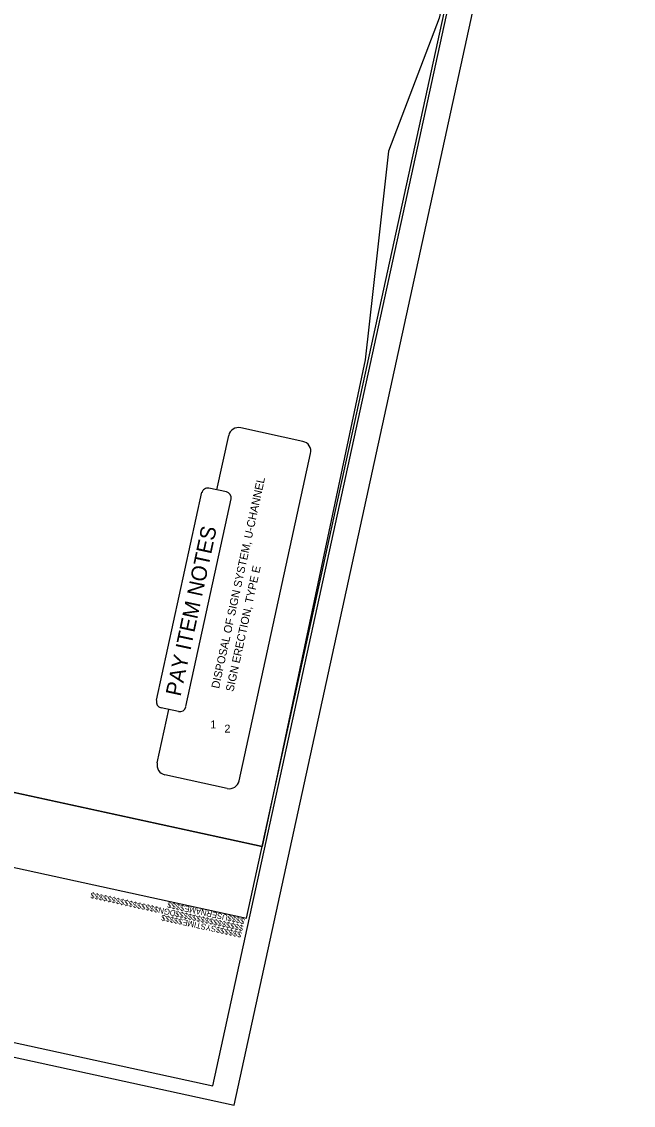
# Model space of a CAD drawing. Extents: x 1615829 to 1617263, y 900664 to 902544.
# Drawn here: x 1616713 to 1617263, y 900664 to 901639 of the extents above; entities that cross this region are included whole.
import ezdxf

# ---------------------------------------------------------------- set-up
doc = ezdxf.new("R2010")
doc.units = 0
for name, color, linetype in [('CTL Primary Horizontal and Vertical CELL', 7, 'Continuous'), ('CTL Primary Horizontal and Vertical Cogo Number', 7, 'Continuous'), ('CTL Secondary Horizontal and Vertical CELL', 7, 'Continuous'), ('Default', 7, 'Continuous'), ('Exist DTM Crownline Cogo Number', 7, 'Continuous'), ('Exist Roads Curbs Cogo Point CELL', 7, 'Continuous'), ('Exist Structure Minor Pipes RCP 18 Inch Cogo Point CELL', 7, 'Continuous')]:
    doc.layers.add(name, color=color, linetype=linetype)

msp = doc.modelspace()

# ---------------------------------------------------------------- linework, layer by layer
at = {"layer": 'CTL Primary Horizontal and Vertical CELL'}
msp.add_lwpolyline([(1616208.96, 902534.66), (1615853.55, 900906.5), (1616884.38, 900681.48), (1617239.79, 902309.64)], close=True, dxfattribs=at)
at = {"layer": 'CTL Primary Horizontal and Vertical Cogo Number'}
msp.add_lwpolyline([(1616187.99, 902543.84), (1615828.85, 900898.58), (1616903.54, 900663.99), (1617262.68, 902309.25)], close=True, dxfattribs=at)
at = {"layer": 'CTL Secondary Horizontal and Vertical CELL'}
msp.add_lwpolyline([(1616208.79, 902521.9), (1615888.89, 901056.41), (1616914.73, 900832.48), (1617234.63, 902297.97)], close=True, dxfattribs=at)
at = {"layer": 'Exist DTM Crownline Cogo Number'}
msp.add_lwpolyline([(1616850.42, 902379.94), (1617227.49, 902296.2), (1617121.36, 901790.43), (1617088.18, 901641.75), (1617042.44, 901522.26), (1617032.35, 901430.63), (1617021.35, 901334.38), (1616928.77, 900896.77), (1615902.83, 901120.28), (1615974.27, 901386.7), (1616087.67, 901888.92), (1616145.49, 901879.24), (1616184.12, 901827.49), (1616138.37, 901614.97), (1616150.59, 901618.07), (1616181.32, 901620.66), (1616299.19, 901764.2), (1616120.07, 901933.32), (1616161.35, 902112.51), (1616179.69, 902310.42), (1616356.27, 902284.95), (1616372.44, 902359.01)], close=True, dxfattribs=at)
at = {"layer": 'Exist Roads Curbs Cogo Point CELL'}
msp.add_line((1615902.83, 901120.28), (1616928.77, 900896.77), dxfattribs=at)
at = {"layer": 'Exist Structure Minor Pipes RCP 18 Inch Cogo Point CELL'}
for p, q in [((1616965.48, 901261.18), (1616909.58, 901273.38)), ((1616888.09, 901217.53), (1616898.76, 901266.44)), ((1616908.15, 900955.93), (1616972.42, 901250.36)), ((1616896.68, 901215.65), (1616881.02, 901219.07)), ((1616834.49, 900972.01), (1616844.97, 901020.02)), ((1616853.56, 901018.14), (1616837.91, 901021.56)), ((1616897.33, 900948.99), (1616841.43, 900961.19))]:
    msp.add_line(p, q, dxfattribs=at)
for points in [[(1616833.84, 901028.5), (1616874.63, 901215.35)], [(1616860.15, 901022.76), (1616900.94, 901209.61)]]:
    msp.add_lwpolyline(points, dxfattribs=at)
for centre, radius, start, end in [((1616907.64, 901264.5), 9.09, 77.68623, 167.68623), ((1616963.54, 901252.3), 9.09, 347.68623, 77.68623), ((1616879.86, 901213.74), 5.45, 77.68623, 167.68623), ((1616895.51, 901210.33), 5.45, 347.68623, 77.68623), ((1616839.07, 901026.89), 5.45, 167.68623, 257.68623), ((1616854.73, 901023.47), 5.45, 257.68623, 347.68623), ((1616843.37, 900970.07), 9.09, 167.68623, 257.68623), ((1616899.27, 900957.87), 9.09, 257.68623, 347.68623)]:
    msp.add_arc(centre, radius, start, end, dxfattribs=at)

# ---------------------------------------------------------------- texts
at = {"layer": 'CTL Secondary Horizontal and Vertical CELL'}
for s, p in [('$$$$$$$$$$$$$$$$DGN$$$$$$$$$$$$$$$$', (1616912.38, 900825.68)), ('$$$$USERNAME$$$$', (1616913.62, 900831.85)), ('$$$$$$SYSTIME$$$$$', (1616910.89, 900819.81))]:
    msp.add_text(s, height=5.25, rotation=167.68623, dxfattribs=at).set_placement(p)
at = {"layer": 'Default'}
for s, height, rotation, p in [('DISPOSAL OF SIGN SYSTEM, U-CHANNEL', 7.1994, 77.68623, (1616890.04, 901038.4)), ('PAY ITEM NOTES', 13.8661, 77.86847, (1616855.42, 901031.24)), ('SIGN ERECTION, TYPE E', 7.1994, 77.68623, (1616902.95, 901035.58)), ('1', 7.2, 359.97341, (1616882.2, 901002.98)), ('2', 7.2, 359.97341, (1616894.9, 900999.2))]:
    msp.add_text(s, height=height, rotation=rotation, dxfattribs=at).set_placement(p)

doc.saveas('drawing.dxf')
